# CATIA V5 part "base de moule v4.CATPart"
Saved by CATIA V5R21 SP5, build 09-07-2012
Part number: base de moule v4
Bounding box of the stored display mesh (mm): x -74.81 to 94.81, y -84.81 to 84.81, z -5 to 19
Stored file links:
  \\salsa.univ-amu.fr\dfs\myhome_etud\DOSSIERS_WINDOWS\Documents\stage s4\CAO\v4\base de moule v4.CATPart
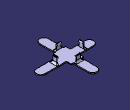
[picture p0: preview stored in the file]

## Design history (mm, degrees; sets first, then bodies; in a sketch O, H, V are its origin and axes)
Body1 (main body)
  Sketch1 on xy-plane, origin (0, 0, 0), H (1, 0, 0), V (0, 1, 0)
    line L1 (-62.5, 12.5) -> (-12.5, 12.5)
    line L2 (-12.5, 12.5) -> (-12.5, 72.5)
    line L3 (12.5, 72.5) -> (12.5, 12.5)
    line L4 (12.5, 12.5) -> (82.5, 12.5)
    line L5 (82.5, -12.5) -> (12.5, -12.5)
    line L6 (12.5, -12.5) -> (12.5, -72.5)
    line L7 (-12.5, -72.5) -> (-12.5, -12.5)
    line L8 (-12.5, -12.5) -> (-62.5, -12.5)
    arc A1 centre (0, -72.5) radius 12.5 from (-12.5, -72.5) to (12.5, -72.5) ccw
    point P14 (71, 0)
    arc A2 centre (0, 72.5) radius 12.5 from (12.5, 72.5) to (-12.5, 72.5) ccw
    point P15 (0, 72.5)
    point P16 (12.5, 72.5)
    arc A3 centre (82.5, 0) radius 12.5 from (82.5, -12.5) to (82.5, 12.5) ccw
    point P18 (82.5, 0)
    arc A4 centre (-62.5, 0) radius 12.5 from (-62.5, 12.5) to (-62.5, -12.5) ccw
    point P20 (-62.5, 0)
    distance L4 L5 = 25
    distance L8 L1 = 25
    distance L6 L7 = 25
    distance L3 L2 = 25
    radius A1 = 12.5
    length L6 = 60
    length L4 = 70
    length L5 = 70
    length L1 = 50
    length L8 = 50
    length L3 = 60
    length L2 = 60
    distance A2 A1 = 170
    horizontal: L1 H, L4 H, L5 H, L8 H
    vertical: L2 V, L3 V, L6 V, L7 V
    symmetry: L5 L4 H, L8 L1 H, L6 L7 V, L3 L2 V
    tangency: A1 L2, A2 L3, A3 L4, A4 L1
    coincidence: P14 H, P15 V, P16 L3, P18 H, P20 H
  Pad1: profile Sketch1, direction (0, 0, 1), length 1.5, mirrored extent
  Sketch2 on end face of Pad1, origin (0, 0, 1.5), H (1, 0, 0), V (0, 1, 0)
    line L1 (-18.5, 26.5) -> (18.5, 26.5)
    line L2 (18.5, 26.5) -> (18.5, -26.5)
    line L3 (18.5, -26.5) -> (-18.5, -26.5)
    line L4 (-18.5, -26.5) -> (-18.5, 26.5)
    distance L2 L4 = 37
    distance L3 L1 = 53
    horizontal: L1 H, L3 H
    vertical: L2 V, L4 V
    symmetry: L2 L4 V, L3 L1 H
  Pad2: profile Sketch2, direction (0, 0, -1), length 2
  Sketch3 on start face of Pad1, origin (0, 0, -1.5), H (1, 0, 0), V (0, -1, 0)
    line L1 (67.3, 4.05) -> (74.7, 4.05)
    line L2 (74.7, 4.05) -> (74.7, 1.25)
    line L3 (74.7, 1.25) -> (67.3, 1.25)
    line L4 (67.3, 1.25) -> (67.3, 4.05)
    point P5 (67.3, -1.25)
    line L5 (67.3, -1.25) -> (74.7, -1.25)
    line L6 (74.7, -1.25) -> (74.7, -4.05)
    line L7 (74.7, -4.05) -> (67.3, -4.05)
    line L8 (67.3, -4.05) -> (67.3, -1.25)
    point P7 (74.7, -4.05)
    point P9 (-38.1, -1.25)
    line L9 (-38.1, -1.25) -> (-30.7, -1.25)
    line L10 (-30.7, -1.25) -> (-30.7, -4.05)
    line L11 (-30.7, -4.05) -> (-38.1, -4.05)
    line L12 (-38.1, -4.05) -> (-38.1, -1.25)
    point P11 (-30.7, -4.05)
    point P13 (-30.7, 1.25)
    line L13 (-30.7, 1.25) -> (-38.1, 1.25)
    line L14 (-38.1, 1.25) -> (-38.1, 4.05)
    line L15 (-38.1, 4.05) -> (-30.7, 4.05)
    line L16 (-30.7, 4.05) -> (-30.7, 1.25)
    point P15 (-38.1, 4.05)
    line L17 (-3.7, -66) -> (3.7, -66)
    line L18 (3.7, -66) -> (3.7, -68.8)
    line L19 (3.7, -68.8) -> (-3.7, -68.8)
    line L20 (-3.7, -68.8) -> (-3.7, -66)
    point P21 (-3.7, -71.3)
    line L21 (-3.7, -71.3) -> (3.7, -71.3)
    line L22 (3.7, -71.3) -> (3.7, -74.1)
    line L23 (3.7, -74.1) -> (-3.7, -74.1)
    line L24 (-3.7, -74.1) -> (-3.7, -71.3)
    point P23 (3.7, -74.1)
    point P25 (3.7, 66)
    line L25 (3.7, 66) -> (-3.7, 66)
    line L26 (-3.7, 66) -> (-3.7, 68.8)
    line L27 (-3.7, 68.8) -> (3.7, 68.8)
    line L28 (3.7, 68.8) -> (3.7, 66)
    point P27 (-3.7, 68.8)
    point P29 (3.7, 74.1)
    line L29 (3.7, 74.1) -> (-3.7, 74.1)
    line L30 (-3.7, 74.1) -> (-3.7, 71.3)
    line L31 (-3.7, 71.3) -> (3.7, 71.3)
    line L32 (3.7, 71.3) -> (3.7, 74.1)
    point P31 (-3.7, 71.3)
    distance L16 L4 = 98
    distance L3 L5 = 2.5
    distance H L17 = 66
    distance H L25 = 66
    distance L27 L31 = 2.5
    distance L19 L21 = 2.5
    length L23 = 7.4
    length L24 = 2.8
    length L20 = 2.8
    length L30 = 2.8
    length L28 = 2.8
    length L6 = 2.8
    length L1 = 7.4
    length L2 = 2.8
    length L11 = 7.4
    distance L16 L26 = 27
    horizontal: L1 H, L3 H, L5 H, L7 H, L9 H, L11 H, L13 H, L15 H, L17 H, L19 H, L21 H, L23 H, L25 H, L27 H, L29 H, L31 H
    vertical: L2 V, L4 V, L6 V, L8 V, L10 V, L12 V, L14 V, L16 V, L18 V, L20 V, L22 V, L24 V, L26 V, L28 V, L30 V, L32 V
    coincidence: P5 L4, P7 L2, P9 L5, P11 L7, P13 L10, P13 L3, P15 L12, P15 L1, P21 L20, P23 L18, P25 L18, P27 L20, P29 L28, P31 L26
    symmetry: L18 L20 V, L26 L28 V, L3 L5 H
  Pad3: profile Sketch3, direction (0, 0, -1), length 3.5
  Sketch4 on face of Pad2, origin (0, 0, 1.5), H (1, 0, 0), V (0, 1, 0)
    line L1 (-40.75, 6) -> (-38.75, 6)
    line L2 (-38.75, 6) -> (-38.75, -6)
    line L3 (-38.75, -6) -> (-40.75, -6)
    line L4 (-40.75, -6) -> (-40.75, 6)
    point P5 (38.75, -6)
    line L5 (38.75, -6) -> (40.75, -6)
    line L6 (40.75, -6) -> (40.75, 6)
    line L7 (40.75, 6) -> (38.75, 6)
    line L8 (38.75, 6) -> (38.75, -6)
    point P7 (40.75, 6)
    line L9 (-6, -28.75) -> (6, -28.75)
    line L10 (6, -28.75) -> (6, -30.75)
    line L11 (6, -30.75) -> (-6, -30.75)
    line L12 (-6, -30.75) -> (-6, -28.75)
    point P13 (-6, 28.75)
    line L13 (-6, 28.75) -> (6, 28.75)
    line L14 (6, 28.75) -> (6, 30.75)
    line L15 (6, 30.75) -> (-6, 30.75)
    line L16 (-6, 30.75) -> (-6, 28.75)
    point P15 (6, 30.75)
    distance V L2 = 38.75
    distance V L8 = 38.75
    distance H L9 = 28.75
    length L11 = 12
    length L10 = 2
    length L14 = 2
    length L5 = 2
    length L3 = 2
    length L6 = 12
    horizontal: L1 H, L3 H, L5 H, L7 H, L9 H, L11 H, L13 H, L15 H
    vertical: L2 V, L4 V, L6 V, L8 V, L10 V, L12 V, L14 V, L16 V
    coincidence: P5 L3, P7 L1, P13 L12, P15 L10
    symmetry: L9 L13 H, L12 L10 V, L5 L7 H
  Pad4: profile Sketch4, direction (0, 0, 1), length 17.5
  Sketch5 on face of Pad4 from Sketch4.L5, origin (0, -6, 0), H (1, 0, 0), V (0, 0, 1)
    line L1 (38.75, 19) -> (38.65, 19)
    line L2 (38.65, 14) -> (38.75, 14)
    line L3 (38.75, 14) -> (38.75, 19)
    reference projected line E1 (12.5, 1.5) -> (82.5, 1.5) from edge [face of Pad1 from Sketch1.L5 | face of Pad2]
    reference projected line E2 (40.75, 1.5) -> (40.75, 19) from edge [face of Pad4 from Sketch4.L6 | face of Pad4 from Sketch4.L5]
    arc A1 centre (38.65, 16.5) radius 2.5 from (38.65, 14) to (38.65, 19) cw
    line L4 (-38.75, 19) -> (-38.65, 19)
    line L5 (-38.65, 14) -> (-38.75, 14)
    line L6 (-38.75, 14) -> (-38.75, 19)
    reference projected line E3 (-62.5, 1.5) -> (-12.5, 1.5) from edge [face of Pad1 from Sketch1.L8 | face of Pad2]
    reference projected line E4 (-40.75, 1.5) -> (-40.75, 19) from edge [face of Pad4 from Sketch4.L3 | face of Pad4 from Sketch4.L4]
    arc A2 centre (-38.65, 16.5) radius 2.5 from (-38.65, 19) to (-38.65, 14) cw
    distance L2 E1 = 12.5
    length L3 = 5
    distance L3 E2 = 2
    distance L5 E3 = 12.5
    length L6 = 5
    distance L6 E4 = 2
    length L1 = 0.1
    length L2 = 0.1
    length L4 = 0.1
    radius A2 = 2.5
    horizontal: L1 H, L2 H, L4 H, L5 H
    tangency: A1 L1, A2 L4
    vertical: L6 V
  Pad5: profile Sketch5, direction (0, 1, 0), length 12
  Sketch6 on face of Pad4 from Sketch4.L16, origin (-6, 0, 0), H (0, -1, 0), V (0, 0, 1)
    line L1 (-28.75, 19) -> (-28.55, 19)
    line L2 (-28.55, 14) -> (-28.75, 14)
    line L3 (-28.75, 14) -> (-28.75, 19)
    reference projected line E1 (-72.5, 1.5) -> (-12.5, 1.5) from edge [face of Pad1 from Sketch1.L2 | face of Pad2]
    reference projected line E2 (-30.75, 1.5) -> (-30.75, 19) from edge [face of Pad4 from Sketch4.L16 | face of Pad4 from Sketch4.L15]
    arc A1 centre (-28.55, 16.5) radius 2.5 from (-28.55, 14) to (-28.55, 19) ccw
    line L4 (28.75, 19) -> (28.55, 19)
    line L5 (28.55, 14) -> (28.75, 14)
    line L6 (28.75, 14) -> (28.75, 19)
    reference projected line E3 (12.5, 1.5) -> (72.5, 1.5) from edge [face of Pad1 from Sketch1.L7 | face of Pad2]
    reference projected line E4 (30.75, 1.5) -> (30.75, 19) from edge [face of Pad4 from Sketch4.L11 | face of Pad4 from Sketch4.L12]
    arc A2 centre (28.55, 16.5) radius 2.5 from (28.55, 19) to (28.55, 14) ccw
    distance L2 E1 = 12.5
    length L3 = 5
    distance L3 E2 = 2
    length L1 = 0.2
    radius A1 = 2.5
    distance L5 E3 = 12.5
    length L6 = 5
    distance L6 E4 = 2
    radius A2 = 2.5
    length L4 = 0.2
    horizontal: L1 H, L2 H, L4 H, L5 H
    vertical: L3 V, L6 V
    tangency: A1 L2, A2 L4
  Pad6: profile Sketch6, direction (1, 0, 0), length 12
  Chamfer1: length 1, angle 45, on edge [face of Pad4 from Sketch4.L11 | face of Pad6]; edge [face of Pad4 from Sketch4.L6 | face of Pad5]; edge [face of Pad4 from Sketch4.L15 | face of Pad6]; edge [face of Pad4 from Sketch4.L4 | face of Pad5]
  Fillet1: radius 5, on edge [face of Pad2 | face of Pad4 from Sketch4.L6]; edge [face of Pad2 | face of Pad5] (x4); edge [face of Pad2 | face of Pad6] (x4); edge [face of Pad2 | face of Pad4 from Sketch4.L11]; edge [face of Pad2 | face of Pad4 from Sketch4.L4]; edge [face of Pad2 | face of Pad4 from Sketch4.L15]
